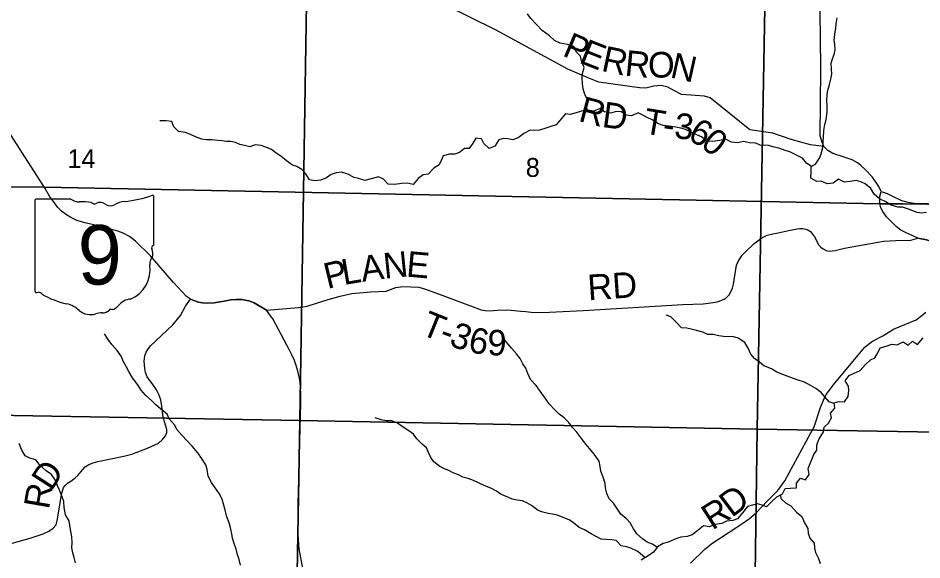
# Model space of a CAD drawing. Extents: x -3.6 to 34, y 0 to 32.8.
# Drawn here: x -2.413 to -0.41, y 29.806 to 31.007 of the extents above; entities that cross this region are included whole.
import ezdxf

# ---------------------------------------------------------------- set-up
doc = ezdxf.new("R2010")
doc.units = 0
for name, color, linetype in [('GM_X_Corporation', 7, 'Continuous'), ('GM_X_County_Road', 7, 'Continuous'), ('GM_X_County_Road_Text', 7, 'Continuous'), ('GM_X_Minor_River', 7, 'Continuous'), ('GM_X_Section_Text', 7, 'Continuous'), ('GM_X_State_Location', 7, 'Continuous'), ('GM_X_State_Route', 7, 'Continuous'), ('GM_X_State_Shield', 7, 'Continuous'), ('GM_X_Township_Road', 7, 'Continuous'), ('GM_X_Township_Road_Text', 7, 'Continuous')]:
    doc.layers.add(name, color=color, linetype=linetype)

msp = doc.modelspace()

# ---------------------------------------------------------------- linework, layer by layer
at = {"layer": 'GM_X_Corporation'}
for points in [[(3.1705, 30.458), (3.1705, 32.8429), (-3.6295, 32.8429), (-3.6295, 30.6462), (-3.5736, 30.6453), (-2.8007, 30.6338), (-2.7027, 30.634), (-2.3541, 30.6318), (-0.5034, 30.5954), (-0.453, 30.5952), (-0.398, 30.5946), (0.2583, 30.5905), (0.2578, 30.5133), (0.3556, 30.5115), (0.4055, 30.5105), (1.2437, 30.4948), (1.7819, 30.4857), (3.0419, 30.4594)], [(-1.7722, 31.1326), (-1.7886, 30.1145), (-2.8032, 30.1329), (-2.786, 31.1483)], [(-1.7722, 31.1326), (-0.7569, 31.1125), (-0.7755, 30.0957), (-1.7886, 30.1145)], [(-0.7569, 31.1125), (0.2635, 31.0982), (0.262, 31.0128), (0.2459, 30.0789), (-0.7755, 30.0957)], [(-1.7886, 30.1145), (-1.8059, 29.1018), (-2.8121, 29.1143), (-2.8032, 30.1329)], [(-0.7755, 30.0957), (-0.7893, 29.0771), (-1.7854, 29.1006), (-1.8059, 29.1018), (-1.7886, 30.1145)], [(-0.7755, 30.0957), (0.2459, 30.0789), (0.244, 29.9924), (0.223, 29.0627), (-0.7627, 29.0764), (-0.7893, 29.0771)]]:
    msp.add_lwpolyline(points, close=True, dxfattribs=at)
msp.add_lwpolyline([(-0.398, 30.5946), (-0.453, 30.5952), (-0.5034, 30.5954), (-2.3541, 30.6318), (-2.7027, 30.634), (-2.8007, 30.6338), (-2.8012, 30.524), (-2.8047, 30.129), (-2.8073, 29.6484), (-2.813, 28.9119), (-2.8208, 28.0589), (-2.8426, 27.1), (-2.8499, 26.4099), (-2.8635, 26.0429), (2.3706, 26.0429)], dxfattribs=at)
at = {"layer": 'GM_X_County_Road'}
for points in [[(-0.4899, 30.5682), (-0.497, 30.5779), (-0.5015, 30.5862), (-0.5032, 30.5948), (-0.5033, 30.6121), (-0.5007, 30.6224), (-0.5056, 30.6333), (-0.5199, 30.6541), (-0.5364, 30.6722), (-0.5455, 30.6798), (-0.5532, 30.6858), (-0.5647, 30.6926), (-0.5848, 30.6993), (-0.6077, 30.7069), (-0.6188, 30.7133), (-0.6276, 30.7221), (-0.6312, 30.7318), (-0.6353, 30.7462), (-0.6343, 30.8916), (-0.6343, 30.9209), (-0.6349, 30.9383), (-0.6354, 31.0419)], [(-0.5007, 30.6224), (-0.4869, 30.6177), (-0.475, 30.6121), (-0.4555, 30.6028), (-0.441, 30.5991), (-0.4222, 30.5962), (-0.3959, 30.5957)], [(-0.4192, 30.5192), (-0.4315, 30.5249), (-0.4448, 30.5309), (-0.4566, 30.5371), (-0.4673, 30.545), (-0.4799, 30.5572), (-0.4887, 30.5666), (-0.4899, 30.5682)], [(-0.3669, 30.4082), (-0.3655, 30.4152), (-0.3601, 30.4429), (-0.3589, 30.4521), (-0.358, 30.4613), (-0.3583, 30.473), (-0.359, 30.4776), (-0.3619, 30.4858), (-0.3664, 30.4937), (-0.3704, 30.498), (-0.3799, 30.5066), (-0.3903, 30.5123), (-0.4, 30.5155), (-0.4192, 30.5192)], [(-0.9225, 29.7987), (-0.8913, 29.8296), (-0.8763, 29.8416), (-0.8621, 29.8512), (-0.8561, 29.855), (-0.8178, 29.8797), (-0.8068, 29.8875), (-0.7921, 29.8973), (-0.7776, 29.9099), (-0.753, 29.9358), (-0.7297, 29.9594), (-0.7136, 29.981), (-0.6559, 30.0877), (-0.649, 30.1011), (-0.6348, 30.1433), (-0.6283, 30.16), (-0.6219, 30.1721), (-0.6041, 30.1965), (-0.5363, 30.2775), (-0.5284, 30.2843), (-0.5194, 30.2906), (-0.4967, 30.3028), (-0.4733, 30.3174), (-0.4228, 30.3382), (-0.4105, 30.3472), (-0.4016, 30.3547)]]:
    msp.add_lwpolyline(points, dxfattribs=at)
at = {"layer": 'GM_X_Minor_River'}
for points in [[(-0.7682, 30.725), (-0.7783, 30.7294), (-0.7919, 30.7306), (-0.8052, 30.7331), (-0.8188, 30.7302), (-0.8317, 30.7319), (-0.8451, 30.7388), (-0.8579, 30.7352), (-0.8733, 30.733), (-0.8859, 30.7343), (-0.8985, 30.7436), (-0.9138, 30.7505), (-0.9237, 30.7549), (-0.9336, 30.7601), (-0.9443, 30.7625), (-0.9553, 30.7654), (-0.9651, 30.7667), (-0.9837, 30.7691), (-0.9936, 30.7727), (-1.0074, 30.7812), (-1.0173, 30.7855), (-1.0269, 30.7907), (-1.0387, 30.7969), (-1.0538, 30.7902), (-1.0655, 30.7919), (-1.077, 30.7997), (-1.0895, 30.7991), (-1.1, 30.7963), (-1.1133, 30.7994), (-1.1233, 30.8061), (-1.1372, 30.8005), (-1.1509, 30.8026), (-1.1537, 30.8124), (-1.1513, 30.8261), (-1.1568, 30.8374), (-1.1604, 30.8502), (-1.1621, 30.8608), (-1.1631, 30.8744), (-1.1621, 30.8839), (-1.1582, 30.8976), (-1.1637, 30.9089), (-1.1669, 30.9225), (-1.1758, 30.9322), (-1.1813, 30.9438), (-1.195, 30.9485), (-1.2117, 30.9516), (-1.2239, 30.9571), (-1.2355, 30.9679), (-1.2516, 30.9794), (-1.2763, 31.0063), (-1.284, 31.0164)], [(-0.6555, 30.6777), (-0.6457, 30.6828), (-0.6372, 30.6962), (-0.6332, 30.7061), (-0.63, 30.7202), (-0.6287, 30.7335), (-0.6285, 30.743), (-0.6272, 30.7574), (-0.6255, 30.7707), (-0.6222, 30.7821), (-0.6202, 30.7985), (-0.62, 30.8114), (-0.6206, 30.825), (-0.6201, 30.8368), (-0.6187, 30.8474), (-0.6151, 30.8593), (-0.6119, 30.8718), (-0.6098, 30.8825), (-0.6107, 30.8938), (-0.6109, 30.9067), (-0.6084, 30.9162), (-0.6037, 30.9285), (-0.6023, 30.938), (-0.6028, 30.9482), (-0.6045, 30.958), (-0.6032, 30.9702), (-0.6011, 30.9843), (-0.6001, 30.9945), (-0.5981, 31.0071)], [(-1.1512, 30.8037), (-1.1645, 30.8005), (-1.1765, 30.7972), (-1.1897, 30.7928), (-1.1996, 30.7945), (-1.2092, 30.7838), (-1.2207, 30.7703), (-1.2324, 30.7667), (-1.2437, 30.7631), (-1.2576, 30.7587), (-1.2682, 30.7577), (-1.2784, 30.7587), (-1.2919, 30.7509), (-1.305, 30.7416), (-1.3163, 30.7372), (-1.3273, 30.7393), (-1.3375, 30.7403), (-1.3473, 30.7367), (-1.3562, 30.7233), (-1.369, 30.7181), (-1.3809, 30.7289), (-1.386, 30.7391), (-1.3985, 30.7407), (-1.4051, 30.7296), (-1.4132, 30.7181), (-1.4235, 30.7179), (-1.4343, 30.7087), (-1.4448, 30.7055), (-1.4566, 30.7053), (-1.4705, 30.7012), (-1.4756, 30.6913), (-1.48, 30.6817), (-1.4916, 30.6743), (-1.5039, 30.6609), (-1.5148, 30.6595), (-1.5264, 30.6514), (-1.5375, 30.6379), (-1.5508, 30.6407), (-1.5626, 30.6401), (-1.5788, 30.638), (-1.5928, 30.6389), (-1.6029, 30.6501), (-1.6143, 30.6548), (-1.6301, 30.6504), (-1.6441, 30.6471), (-1.6581, 30.651), (-1.668, 30.6535), (-1.6822, 30.6612), (-1.6962, 30.6651), (-1.708, 30.6642), (-1.7189, 30.6598), (-1.729, 30.6528), (-1.7421, 30.6473), (-1.7553, 30.6463), (-1.7667, 30.6484), (-1.7753, 30.6615), (-1.7842, 30.6712), (-1.7949, 30.6779), (-1.8044, 30.6807), (-1.8178, 30.6907), (-1.8305, 30.7008), (-1.8408, 30.7074), (-1.8515, 30.7156), (-1.8634, 30.721), (-1.874, 30.7246), (-1.8877, 30.7259), (-1.899, 30.7216), (-1.9107, 30.7244), (-1.921, 30.7269), (-1.9306, 30.7313), (-1.9412, 30.733), (-1.9507, 30.7336), (-1.9609, 30.7349), (-1.9704, 30.7355), (-1.9836, 30.7368), (-1.9958, 30.737), (-2.0052, 30.7387), (-2.0159, 30.7423), (-2.0308, 30.7485), (-2.0418, 30.7536), (-2.057, 30.7553), (-2.0674, 30.7661), (-2.0722, 30.7777), (-2.0843, 30.7794), (-2.0983, 30.7788)], [(-0.4, 30.5762), (-0.4106, 30.5741), (-0.4204, 30.5762), (-0.4299, 30.5799), (-0.4395, 30.5831), (-0.4535, 30.5879), (-0.4634, 30.5877), (-0.4782, 30.5924), (-0.4919, 30.6002), (-0.5041, 30.6064), (-0.5157, 30.6165), (-0.5234, 30.6293), (-0.5357, 30.6393), (-0.5452, 30.6441), (-0.5555, 30.647), (-0.5691, 30.6445), (-0.5815, 30.6432), (-0.5952, 30.6498), (-0.6068, 30.6409), (-0.6204, 30.6392), (-0.633, 30.6454), (-0.6432, 30.6449), (-0.6562, 30.6523), (-0.6553, 30.666), (-0.6555, 30.6788), (-0.6654, 30.6844), (-0.675, 30.6964), (-0.6892, 30.7037), (-0.7029, 30.7104), (-0.7132, 30.7136), (-0.7272, 30.7187), (-0.7371, 30.7205), (-0.75, 30.7241), (-0.7682, 30.725)], [(-0.76, 30.2358), (-0.7699, 30.244), (-0.7814, 30.2525), (-0.7891, 30.2622), (-0.795, 30.275), (-0.8028, 30.2874), (-0.8174, 30.297), (-0.8295, 30.3009), (-0.8443, 30.3003), (-0.8599, 30.3027), (-0.8728, 30.3055), (-0.8845, 30.3057), (-0.8956, 30.3108), (-0.9093, 30.314), (-0.9211, 30.3172), (-0.9306, 30.3193), (-0.9431, 30.3202), (-0.9531, 30.3314), (-0.9662, 30.3445), (-0.9769, 30.3481)], [(-1.9225, 29.8069), (-1.9265, 29.8167), (-1.9294, 29.8299), (-1.9333, 29.8397), (-1.9377, 29.854), (-1.9394, 29.8639), (-1.9415, 29.8741), (-1.9448, 29.8877), (-1.9503, 29.9016), (-1.954, 29.9163), (-1.9568, 29.9273), (-1.9604, 29.9401), (-1.9671, 29.9529), (-1.9776, 29.9675), (-1.9842, 29.9772), (-1.9916, 29.9911), (-1.9937, 30.0062), (-1.9969, 30.0164), (-2.0059, 30.0314), (-2.0141, 30.043), (-2.0268, 30.058), (-2.0388, 30.0703), (-2.0488, 30.0815), (-2.0608, 30.0945), (-2.0655, 30.1043), (-2.0778, 30.1185), (-2.0822, 30.1287), (-2.0929, 30.1368), (-2.1071, 30.1495), (-2.1168, 30.1591), (-2.1294, 30.1699), (-2.1399, 30.1819), (-2.1473, 30.1942), (-2.1593, 30.2092), (-2.1667, 30.2216), (-2.1733, 30.2347), (-2.1792, 30.2445), (-2.1843, 30.2577), (-2.1929, 30.27), (-2.2048, 30.2835), (-2.213, 30.2947), (-2.2215, 30.3067)], [(-0.9968, 29.8335), (-1.0067, 29.8408), (-1.0189, 29.8451), (-1.0289, 29.8525), (-1.0419, 29.8633), (-1.0493, 29.8745), (-1.0567, 29.8877), (-1.0652, 29.8974), (-1.0771, 29.907), (-1.0845, 29.9183), (-1.0938, 29.9314), (-1.1027, 29.9415), (-1.1082, 29.9531), (-1.1114, 29.9656), (-1.1116, 29.9751), (-1.116, 29.9894), (-1.1215, 30.0026), (-1.1229, 30.0128), (-1.125, 30.0249), (-1.1362, 30.0402), (-1.1466, 30.0525), (-1.1575, 30.066), (-1.1656, 30.0772), (-1.1749, 30.0892), (-1.1853, 30.1), (-1.1927, 30.1101), (-1.2031, 30.1209), (-1.2138, 30.1291), (-1.2235, 30.1388), (-1.2358, 30.1515), (-1.2466, 30.1664), (-1.2556, 30.1796), (-1.2649, 30.1923), (-1.2776, 30.2057), (-1.2831, 30.2189), (-1.2879, 30.2305), (-1.2941, 30.2403), (-1.3004, 30.2519), (-1.3085, 30.2628), (-1.3197, 30.2751), (-1.3294, 30.2875), (-1.3406, 30.3013)], [(-0.7548, 29.9235), (-0.7432, 29.9345), (-0.7313, 29.9453), (-0.7193, 29.9519), (-0.713, 29.9641), (-0.7013, 29.9647), (-0.6877, 29.9657), (-0.6879, 29.9759), (-0.6793, 29.987), (-0.6679, 29.983), (-0.6602, 29.9953), (-0.6619, 30.0085), (-0.6579, 30.0192), (-0.6542, 30.0287), (-0.6495, 30.0394), (-0.6432, 30.049), (-0.643, 30.0608), (-0.6379, 30.0738), (-0.6283, 30.0895), (-0.6266, 30.1001), (-0.6169, 30.1086), (-0.6102, 30.1208), (-0.6123, 30.1307), (-0.603, 30.1422), (-0.6047, 30.1543), (-0.5945, 30.1571), (-0.5816, 30.1565), (-0.5735, 30.168), (-0.5722, 30.181), (-0.5727, 30.1908), (-0.5801, 30.2028), (-0.5716, 30.2143), (-0.5603, 30.2198), (-0.5468, 30.2253), (-0.5349, 30.2392), (-0.5244, 30.2492), (-0.5143, 30.2535), (-0.508, 30.265), (-0.5025, 30.2757), (-0.4893, 30.2793), (-0.4769, 30.2841), (-0.4651, 30.2824), (-0.4516, 30.2894), (-0.4409, 30.2816), (-0.4308, 30.2908), (-0.4201, 30.2834), (-0.4075, 30.298)], [(-0.6044, 30.1523), (-0.6153, 30.1564), (-0.6249, 30.1669), (-0.633, 30.177), (-0.6453, 30.1855), (-0.6556, 30.1914), (-0.6705, 30.1999), (-0.6845, 30.2043), (-0.6944, 30.2079), (-0.7085, 30.213), (-0.7184, 30.217), (-0.7317, 30.2221), (-0.7436, 30.2296), (-0.76, 30.2358)], [(-1.0235, 29.8106), (-1.0397, 29.8247), (-1.055, 29.832), (-1.0649, 29.8349), (-1.0763, 29.8369), (-1.0875, 29.8485), (-1.097, 29.8506), (-1.1098, 29.8508), (-1.1208, 29.8517), (-1.1331, 29.8587), (-1.143, 29.8638), (-1.1579, 29.8723), (-1.1694, 29.8778), (-1.1817, 29.8882), (-1.1916, 29.8949), (-1.2046, 29.8996), (-1.2175, 29.905), (-1.2285, 29.9075), (-1.238, 29.9088), (-1.2498, 29.9117), (-1.2601, 29.9153), (-1.2754, 29.9264), (-1.2854, 29.9323), (-1.2949, 29.9367), (-1.307, 29.938), (-1.3181, 29.9404), (-1.3288, 29.9456), (-1.3421, 29.951), (-1.3524, 29.9584), (-1.365, 29.9647), (-1.3788, 29.9701), (-1.3925, 29.9763), (-1.4036, 29.9818), (-1.4158, 29.9862), (-1.4272, 29.9894), (-1.4371, 29.9941), (-1.4485, 29.9989), (-1.4585, 30.004), (-1.468, 30.008), (-1.4779, 30.0131), (-1.4913, 30.0231), (-1.498, 30.0329), (-1.5034, 30.0442), (-1.5074, 30.0543), (-1.517, 30.0621), (-1.529, 30.0744), (-1.5363, 30.0842), (-1.5467, 30.0919), (-1.5597, 30.0997), (-1.5719, 30.1086), (-1.5845, 30.1137), (-1.5963, 30.1138), (-1.608, 30.1163), (-1.6217, 30.1206)], [(-2.2854, 29.7996), (-2.2887, 29.8109), (-2.2911, 29.8218), (-2.2932, 29.8328), (-2.293, 29.8449), (-2.2936, 29.8571), (-2.2962, 29.8729), (-2.2995, 29.8926), (-2.3077, 29.9057), (-2.3106, 29.9223), (-2.3116, 29.9352), (-2.3148, 29.9454), (-2.3208, 29.9601), (-2.3251, 29.9699), (-2.3291, 29.9808), (-2.3388, 29.9954), (-2.3503, 30.0032), (-2.3637, 30.0154), (-2.3734, 30.0278), (-2.3867, 30.031), (-2.397, 30.0368), (-2.4052, 30.0504), (-2.41, 30.0635)], [(-0.7233, 29.9497), (-0.7225, 29.942), (-0.7125, 29.9323), (-0.7003, 29.9256), (-0.688, 29.9118), (-0.6765, 29.9017), (-0.6699, 29.8878), (-0.6632, 29.8754), (-0.6623, 29.8651), (-0.6584, 29.8538), (-0.6487, 29.8426), (-0.6482, 29.832), (-0.6458, 29.8222), (-0.6391, 29.8086), (-0.6352, 29.7977)], [(-0.7548, 29.9235), (-0.764, 29.9268), (-0.7747, 29.93), (-0.7852, 29.9268), (-0.7962, 29.924), (-0.8073, 29.9101), (-0.8188, 29.8971), (-0.8293, 29.8931), (-0.8429, 29.8913), (-0.8531, 29.8862), (-0.8685, 29.8845), (-0.8813, 29.8789), (-0.8942, 29.881), (-0.9069, 29.8713), (-0.9189, 29.8616), (-0.9302, 29.8576), (-0.9441, 29.8559), (-0.9551, 29.8527), (-0.972, 29.8448), (-0.9833, 29.8419), (-0.9956, 29.8349), (-1.0049, 29.823), (-1.0169, 29.8148), (-1.0322, 29.8051)], [(-1.9201, 29.7941), (-1.9225, 29.8069)]]:
    msp.add_lwpolyline(points, dxfattribs=at)
at = {"layer": 'GM_X_State_Route'}
for points in [[(-2.0305, 30.3837), (-2.0395, 30.3898), (-2.0686, 30.4208), (-2.1195, 30.4797), (-2.1528, 30.5125), (-2.166, 30.5224), (-2.1795, 30.53), (-2.1914, 30.5346), (-2.202, 30.5376), (-2.2228, 30.5427), (-2.2485, 30.549), (-2.2676, 30.5537), (-2.2839, 30.5592), (-2.2954, 30.5646), (-2.3052, 30.5705), (-2.3164, 30.5789), (-2.3244, 30.5873), (-2.3305, 30.5952), (-2.3428, 30.612), (-2.3539, 30.6313), (-2.3713, 30.6578), (-2.4414, 30.7673)], [(-1.8624, 30.3595), (-1.8894, 30.3753), (-1.9015, 30.3798), (-1.9092, 30.3814), (-1.9169, 30.3827), (-1.9297, 30.3829), (-1.9411, 30.382), (-1.9558, 30.3797), (-1.9779, 30.3754), (-1.9929, 30.3746), (-2.0043, 30.3753), (-2.0128, 30.3771), (-2.0233, 30.3806), (-2.0305, 30.3837)], [(-1.7649, 29.6958), (-1.7902, 29.83), (-1.7919, 29.8609), (-1.7919, 29.9288), (-1.7863, 30.1541), (-1.7865, 30.1717), (-1.7871, 30.1886), (-1.7879, 30.1992), (-1.7891, 30.2084), (-1.791, 30.2172), (-1.7925, 30.2241), (-1.7947, 30.2316), (-1.7966, 30.2369), (-1.8005, 30.2476), (-1.8061, 30.2607), (-1.8114, 30.2705), (-1.8481, 30.34), (-1.8545, 30.349), (-1.8624, 30.3595)]]:
    msp.add_lwpolyline(points, dxfattribs=at)
at = {"layer": 'GM_X_State_Shield'}
for p, q in [((-2.3753, 30.6022), (-2.3753, 30.4021)), ((-2.2955, 30.6057), (-2.3728, 30.6057)), ((-2.1117, 30.5059), (-2.1117, 30.6106)), ((-2.1117, 30.506), (-2.1117, 30.5059))]:
    msp.add_line(p, q, dxfattribs=at)
for centre, radius, start, end in [((-2.3723, 30.6026), 0.00305, 98.1301, 188.1301), ((-2.2771, 30.6289), 0.0296, 231.6195, 271.1119), ((-2.2673, 30.4933), 0.1064, 80.4867, 94.9883), ((-2.1699, 30.5445), 0.0563, 97.3462, 120.7689), ((-2.2056, 30.8785), 0.2796, 275.8445, 288.9065), ((-2.1146, 30.6111), 0.00294, 351.8621, 97.738), ((-2.2432, 30.6037), 0.00855, 219.7921, 297.1024), ((-2.2306, 30.5805), 0.0178, 54.4667, 119.1411), ((-2.2077, 30.6123), 0.0214, 233.8562, 294.8282), ((-2.1124, 30.4982), 0.00454, 107.944, 210.337), ((-2.1148, 30.5055), 0.00314, 289.6038, 7.7341), ((-2.1413, 30.485), 0.0273, 340.033, 23.6496), ((-2.1899, 30.4488), 0.0699, 292.3089, 8.9858), ((-2.1012, 30.4621), 0.0198, 136.8065, 186.9296), ((-2.3723, 30.4017), 0.00308, 171.9584, 258.3066), ((-2.3718, 30.4221), 0.0235, 267.339, 280.6039), ((-2.367, 30.3905), 0.00848, 29.7484, 93.2717), ((-2.26, 30.5703), 0.2019, 240.4129, 257.1985), ((-2.1604, 30.3459), 0.0383, 94.4031, 142.5768), ((-2.3202, 30.3122), 0.0632, 47.1842, 75.836), ((-2.2518, 30.3896), 0.0401, 230.7004, 286.2918), ((-2.2257, 30.3746), 0.0214, 268.777, 315.5493), ((-2.2064, 30.3552), 0.00601, 65.7517, 132.6484), ((-2.209, 30.3827), 0.0226, 282.8732, 323.2771), ((-2.2287, 30.3204), 0.0329, 85.6951, 111.2099)]:
    msp.add_arc(centre, radius, start, end, dxfattribs=at)
at = {"layer": 'GM_X_Township_Road'}
for points in [[(-1.1518, 30.8755), (-1.1536, 30.8762), (-1.1945, 30.8935), (-1.3548, 30.9811), (-1.5222, 31.0644), (-1.615, 31.0989), (-1.6323, 31.1049), (-1.6461, 31.1073), (-1.6721, 31.1113), (-1.7708, 31.1202), (-1.7989, 31.127), (-1.7998, 31.127)], [(-0.6276, 30.7221), (-0.657, 30.7259), (-0.6997, 30.738), (-0.7403, 30.7514), (-0.7915, 30.7595), (-0.8795, 30.8301), (-0.8921, 30.8338), (-0.9431, 30.8376), (-0.9582, 30.8458), (-0.9728, 30.8541), (-0.9881, 30.8574), (-1.0044, 30.8558), (-1.0221, 30.8514), (-1.0362, 30.8525), (-1.1257, 30.8645), (-1.1518, 30.8755)], [(-1.8624, 30.3595), (-1.7917, 30.3654), (-1.7723, 30.3686), (-1.7517, 30.3749), (-1.7254, 30.3834), (-1.699, 30.3907), (-1.6729, 30.3961), (-1.6313, 30.3997), (-1.5972, 30.4015), (-1.5755, 30.41), (-1.5599, 30.412), (-1.5244, 30.4104), (-1.5103, 30.4062), (-1.4719, 30.3918), (-1.387, 30.36), (-1.3774, 30.3586), (-1.3679, 30.3582), (-1.3507, 30.3596), (-1.3315, 30.3598), (-1.3202, 30.3593), (-1.299, 30.3575), (-1.2877, 30.3566), (-1.276, 30.3547), (-1.2625, 30.3539), (-1.2349, 30.3548), (-1.1605, 30.3584), (-0.9396, 30.3719), (-0.8947, 30.3737), (-0.8777, 30.3753), (-0.8637, 30.3776), (-0.8534, 30.3814), (-0.845, 30.3856), (-0.8373, 30.3937), (-0.8336, 30.4003), (-0.8299, 30.4079), (-0.8272, 30.4168), (-0.8249, 30.4357), (-0.8206, 30.459), (-0.8171, 30.467), (-0.8138, 30.4733), (-0.8081, 30.4814), (-0.8008, 30.4888), (-0.7827, 30.5063), (-0.765, 30.5195), (-0.753, 30.5254), (-0.7404, 30.5289), (-0.7287, 30.5311), (-0.7023, 30.5364), (-0.6816, 30.5405), (-0.6741, 30.5406), (-0.6646, 30.5384), (-0.6568, 30.5335), (-0.6478, 30.5221), (-0.6385, 30.5038), (-0.6342, 30.4988), (-0.6291, 30.4957), (-0.6226, 30.4919), (-0.6159, 30.4905), (-0.6024, 30.4915), (-0.582, 30.497), (-0.4955, 30.512), (-0.4678, 30.514), (-0.4344, 30.5144), (-0.4192, 30.5192)], [(-0.4192, 30.5192), (-0.4, 30.5155), (-0.3903, 30.5123), (-0.3799, 30.5066), (-0.3704, 30.498), (-0.3664, 30.4937), (-0.3619, 30.4858), (-0.359, 30.4776), (-0.3583, 30.473), (-0.358, 30.4613), (-0.3589, 30.4521), (-0.3601, 30.4429), (-0.3655, 30.4152), (-0.3669, 30.4082)], [(-2.4254, 29.8427), (-2.3856, 29.8538), (-2.3568, 29.8635), (-2.3447, 29.8698), (-2.3347, 29.8759), (-2.3286, 29.8834), (-2.3255, 29.896), (-2.3168, 29.9506), (-2.3135, 29.9611), (-2.3121, 29.9661), (-2.3084, 29.971), (-2.303, 29.9759), (-2.2957, 29.9804), (-2.2866, 29.9868), (-2.28, 29.9931), (-2.2694, 30.0059), (-2.2643, 30.0118), (-2.2562, 30.0175), (-2.2465, 30.0212), (-2.236, 30.0237), (-2.2073, 30.0297), (-2.1784, 30.0355), (-2.1603, 30.0398), (-2.1261, 30.0535), (-2.1015, 30.0648), (-2.0925, 30.0725), (-2.086, 30.0805), (-2.0832, 30.088), (-2.0833, 30.0946), (-2.0879, 30.1116), (-2.0922, 30.1277), (-2.0935, 30.1406), (-2.0949, 30.1509), (-2.0965, 30.1604), (-2.1008, 30.1728), (-2.1056, 30.1826), (-2.1144, 30.1943), (-2.1264, 30.2119), (-2.13, 30.2211), (-2.1316, 30.23), (-2.1324, 30.2381), (-2.1331, 30.2465), (-2.1315, 30.2582), (-2.1289, 30.2666), (-2.1253, 30.2725), (-2.1189, 30.2803), (-2.0698, 30.3271), (-2.0527, 30.3477), (-2.0415, 30.3679), (-2.0305, 30.3837)], [(-2.0305, 30.3837), (-2.0233, 30.3806), (-2.0128, 30.3771), (-2.0043, 30.3753), (-1.9929, 30.3746), (-1.9779, 30.3754), (-1.9558, 30.3797), (-1.9411, 30.382), (-1.9297, 30.3829), (-1.9169, 30.3827), (-1.9092, 30.3814), (-1.9015, 30.3798), (-1.8894, 30.3753), (-1.8624, 30.3595)]]:
    msp.add_lwpolyline(points, dxfattribs=at)

# ---------------------------------------------------------------- texts
at = {"layer": 'GM_X_County_Road_Text'}
for s, rotation, p in [('D', 36.8671, (-0.8315, 29.8983)), ('R', 32.6524, (-0.8745, 29.8706))]:
    msp.add_text(s, height=0.0568, rotation=rotation, dxfattribs=at).set_placement(p)
at = {"layer": 'GM_X_Section_Text'}
for s, height, p in [('14', 0.04186, (-2.3033, 30.6743)), ('8', 0.0419, (-1.2879, 30.6548))]:
    msp.add_text(s, height=height, rotation=0, dxfattribs=at).set_placement(p)
at = {"layer": 'GM_X_State_Location'}
for s in ['s', 'r']:
    msp.add_text(s, height=0.000189, dxfattribs=at).set_placement((-2.2465, 30.4889))
msp.add_text('9', height=0.000189, rotation=0, dxfattribs=at).set_placement((-2.275, 30.4751))
at = {"layer": 'GM_X_State_Shield'}
msp.add_text('9', height=0.1318, dxfattribs=at).set_placement((-2.2806, 30.4162))
at = {"layer": 'GM_X_Township_Road_Text'}
for s, height, rotation, p in [('P', 0.0568, 336.875, (-1.2087, 30.9245)), ('E', 0.0568, 338.4541, (-1.1719, 30.9088)), ('R', 0.0568, 348.0938, (-1.1224, 30.8902)), ('R', 0.0568, 354.3556, (-1.07, 30.8795)), ('O', 0.0568, 0.7707, (-1.0166, 30.8746)), ('N', 0.0568, 347.503, (-0.9701, 30.8757)), ('R', 0.0568, 345.0483, (-1.1731, 30.7792)), ('D', 0.0568, 352.1754, (-1.1206, 30.7657)), ('T', 0.0568, 350.6088, (-1.0295, 30.7517)), ('3', 0.0568, 354.4659, (-0.9604, 30.7407)), ('6', 0.0568, 330.3358, (-0.9316, 30.7392)), ('-', 0.0568, 351.3234, (-0.9868, 30.7446)), ('0', 0.0568, 321.6645, (-0.903, 30.7232)), ('A', 0.0568, 8.0255, (-1.6498, 30.422)), ('N', 0.0568, 5.8164, (-1.6008, 30.4289)), ('E', 0.0568, 355.0097, (-1.5539, 30.434)), ('P', 0.0568, 13.7078, (-1.7274, 30.4062)), ('L', 0.0568, 9.5152, (-1.6913, 30.415)), ('RD', 0.05682, 3.9458, (-1.149, 30.381)), ('T', 0.0568, 338.0434, (-1.5232, 30.3066)), ('3', 0.0568, 339.9091, (-1.46, 30.2819)), ('6', 0.0568, 349.2245, (-1.4174, 30.2672)), ('-', 0.0568, 339.5795, (-1.4822, 30.2901)), ('9', 0.0568, 358.2376, (-1.3734, 30.2596)), ('D', 0.0568, 57.0667, (-2.3387, 29.9567)), ('R', 0.0568, 80.2184, (-2.3444, 29.9163))]:
    msp.add_text(s, height=height, rotation=rotation, dxfattribs=at).set_placement(p)

doc.saveas('drawing.dxf')
